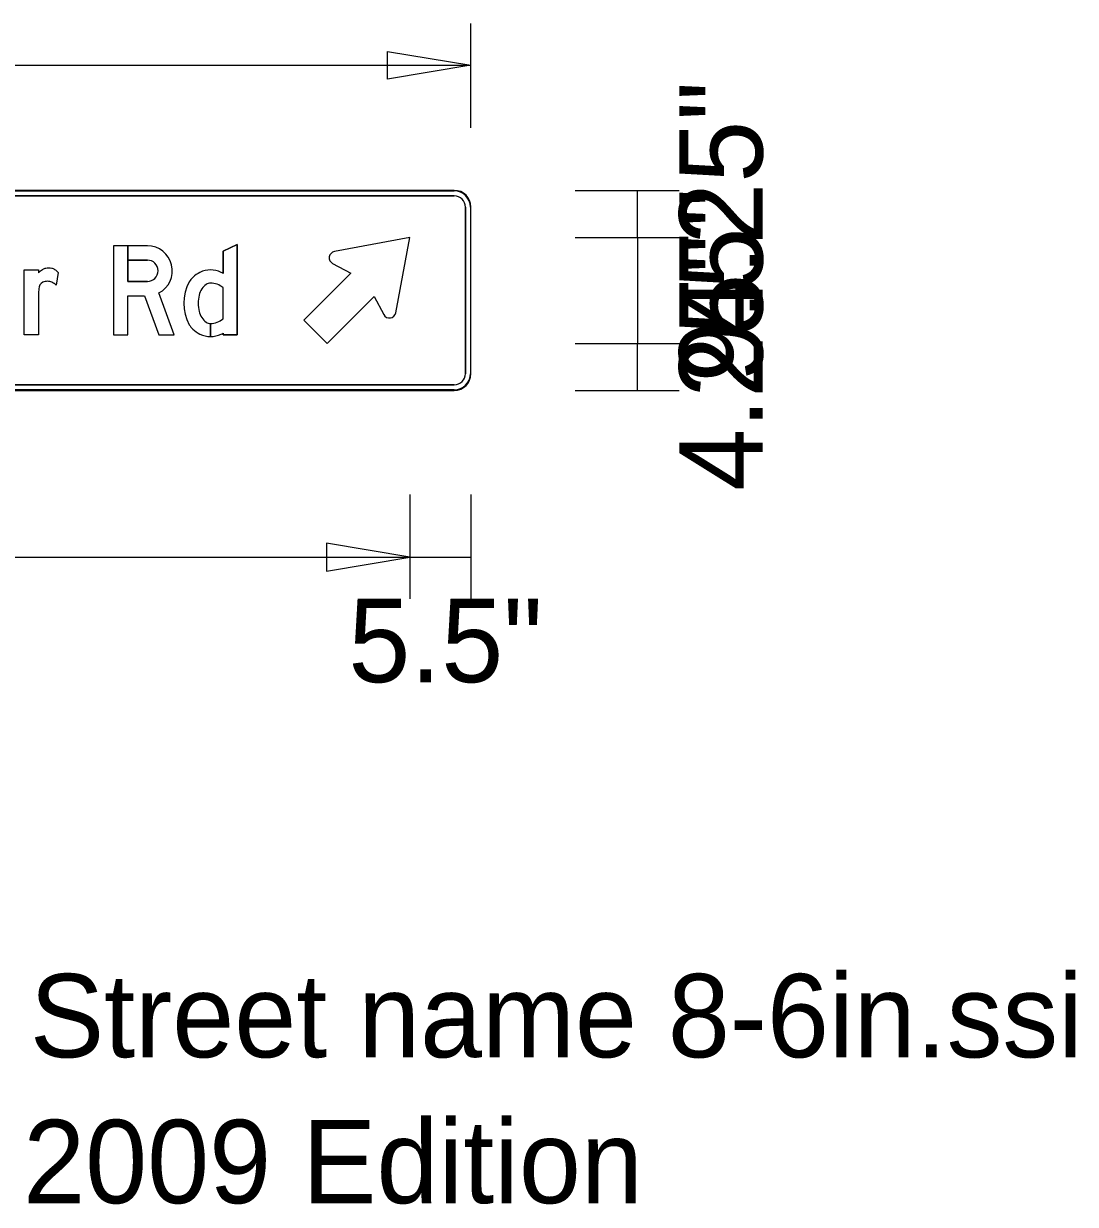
# Model space of a CAD drawing. Extents: x 914742 to 915492, y 328736 to 329423.
# Drawn here: x 915005.88 to 915013.77, y 328736.13 to 328744.99 of the extents above; entities that cross this region are included whole.
import ezdxf

# ---------------------------------------------------------------- set-up
doc = ezdxf.new("R2010")
doc.units = 0
for name, color, linetype in [('GSBWFILL', 7, 'Continuous'), ('GSCOLORFILL', 7, 'Continuous'), ('GSDIMS', 7, 'Continuous'), ('GSOUTLINE', 7, 'Continuous')]:
    doc.layers.add(name, color=color, linetype=linetype)

msp = doc.modelspace()

# ---------------------------------------------------------------- linework, layer by layer
at = {"layer": 'GSBWFILL'}
for p, q in [((915009.1129, 328743.7353), (915001.3629, 328743.7353)), ((915001.3629, 328743.6937), (915009.1129, 328743.6937)), ((915009.1962, 328743.6103), (915009.1962, 328742.3603)), ((915009.2379, 328742.3603), (915009.2379, 328743.6103)), ((915006.1423, 328743.1191), (915006.1281, 328743.0252)), ((915006.1423, 328743.1191), (915006.1423, 328743.1191)), ((915009.1129, 328742.277), (915001.3633, 328742.277)), ((915001.3633, 328742.2353), (915009.1129, 328742.2353))]:
    msp.add_line(p, q, dxfattribs=at)
for points in [[(915006.8121, 328743.052), (915006.6656, 328743.052), (915006.6656, 328743.3187), (915006.5589, 328743.3187), (915006.5589, 328742.652), (915006.6656, 328742.652), (915006.6656, 328742.9453), (915006.7908, 328742.9453), (915006.8986, 328742.652), (915007.0123, 328742.652), (915006.897, 328742.9657)], [(915006.6656, 328743.3187), (915006.6656, 328743.212), (915006.8121, 328743.212)], [(915006.8121, 328743.3187), (915006.6656, 328743.3187)], [(915007.3789, 328743.1129), (915007.3789, 328743.2787), (915007.4856, 328743.3303), (915007.4856, 328742.652), (915007.3789, 328742.652), (915007.3789, 328742.6644)], [(915008.6744, 328742.8173), (915008.7802, 328743.3826), (915008.2149, 328743.2768)], [(915005.9956, 328742.9572), (915005.9956, 328742.652), (915005.8889, 328742.652), (915005.8889, 328743.1387), (915005.9956, 328743.1387), (915005.9956, 328743.1168)], [(915008.2012, 328743.187), (915008.3374, 328743.1148), (915007.9856, 328742.763)], [(915007.3789, 328742.772), (915007.3789, 328743.0053)], [(915007.9856, 328742.763), (915008.1606, 328742.588), (915008.5124, 328742.9398), (915008.5846, 328742.8036)], [(915007.2856, 328742.737), (915007.2856, 328742.6387)], [(915007.2856, 328742.6387), (915007.2856, 328742.737)]]:
    msp.add_lwpolyline(points, dxfattribs=at)
for centre, radius, start, end in [((915009.1129, 328743.6103), 0.125, 0, 90), ((915009.1129, 328743.6103), 0.0833, 0, 90), ((915008.2237, 328743.2295), 0.0481, 100.60026, 242.05729), ((915008.6271, 328742.8262), 0.0481, 207.94271, 349.39974), ((915009.1129, 328742.3603), 0.125, 270, 0), ((915009.1129, 328742.3603), 0.0833, 270, 0)]:
    msp.add_arc(centre, radius, start, end, dxfattribs=at)
for centre, major_axis, ratio, start_param, end_param in [((915006.8121, 328743.132), (0, 0.1867), 0.999999, 3.613317, 6.283185), ((915006.8121, 328743.132), (0, 0.08), 0.999999, 3.141593, 6.283185), ((915006.1238, 328742.9889), (0, 0.181), 0.999992, 0.581368, 0.786698), ((915006.061, 328743.0845), (0, 0.0667), 0.999992, 0.152837, 0.581368), ((915006.0713, 328743.0175), (0, 0.1345), 0.999992, 0, 0.152837), ((915006.0713, 328743.0272), (0, 0.1248), 0.999992, 6.089185, 6.283185), ((915006.0825, 328743.0842), (0, 0.0667), 0.999992, 5.719052, 6.089185), ((915006.0648, 328743.0563), (0, 0.0997), 0.999992, 5.39423, 5.719052), ((915007.3019, 328742.9243), (0, 0.2181), 0.999993, 0.454071, 0.759609), ((915007.2856, 328742.9577), (0, 0.181), 0.999993, 6.283185, 6.737256), ((915007.2856, 328742.9577), (0, 0.181), 0.999993, 5.829115, 6.283185), ((915007.2693, 328742.9243), (0, 0.2181), 0.999993, 5.756638, 5.829115), ((915006.0535, 328742.9975), (0, 0.0558), 0.999992, 0.483758, 1.563151), ((915006.0642, 328742.9461), (0, 0.1073), 0.999992, 0, 0.348596), ((915006.0642, 328742.9752), (0, 0.0783), 0.999992, 5.88958, 6.283185), ((915006.0091, 328742.8806), (0, 0.1873), 0.999992, 5.594805, 5.811282), ((915007.4232, 328742.8887), (0, 0.3376), 0.999993, 1.075368, 2.066224), ((915007.2435, 328742.9858), (0, 0.1333), 0.999993, 0.759609, 1.075368), ((915007.3154, 328742.937), (0, 0.1124), 0.999993, 0.592441, 1.019141), ((915007.2856, 328742.9812), (0, 0.0591), 0.999993, 6.283185, 6.875627), ((915007.2856, 328742.8984), (0, 0.1419), 0.999993, 5.565644, 6.283185), ((915006.3983, 328742.9572), (0, 0.4026), 0.999992, 1.469323, 1.570796), ((915007.4379, 328742.8887), (0, 0.2456), 0.999993, 1.321211, 1.570796), ((915007.3628, 328742.9078), (0, 0.1681), 0.999993, 1.019141, 1.321211), ((915007.4379, 328742.8887), (0, 0.2456), 0.999993, 1.570796, 1.820382), ((915007.3628, 328742.8695), (0, 0.1681), 0.999993, 1.820382, 2.122451), ((915007.3154, 328742.8403), (0, 0.1124), 0.999993, 2.122451, 2.549151), ((915007.2856, 328742.8789), (0, 0.1419), 0.999993, 3.14171, 3.859134), ((915007.2435, 328742.7915), (0, 0.1333), 0.999993, 2.066224, 2.381983), ((915007.3019, 328742.853), (0, 0.2181), 0.999993, 2.381983, 2.687522), ((915007.2856, 328742.7961), (0, 0.0591), 0.999993, 2.549151, 3.141593), ((915007.2856, 328742.8197), (0, 0.181), 0.999993, 2.687522, 3.141593), ((915007.2856, 328742.8197), (0, 0.181), 0.999993, 3.141685, 3.595663), ((915007.2693, 328742.853), (0, 0.2181), 0.999993, 3.595663, 3.66814)]:
    msp.add_ellipse(centre, major_axis=major_axis, ratio=ratio, start_param=start_param, end_param=end_param, dxfattribs=at)
at = {"layer": 'GSCOLORFILL'}
for p, q in [((915009.1129, 328743.7353), (915001.3629, 328743.7353)), ((915009.1129, 328743.7353), (915001.3629, 328743.7353)), ((915009.1129, 328743.7353), (915001.3629, 328743.7353)), ((915001.3629, 328743.7312), (915009.1129, 328743.7312)), ((915001.3629, 328743.6937), (915009.1129, 328743.6937)), ((915009.1962, 328743.6103), (915009.1962, 328742.3603)), ((915009.2337, 328743.6103), (915009.2337, 328742.3603)), ((915009.2379, 328742.3603), (915009.2379, 328743.6103)), ((915009.2379, 328742.3603), (915009.2379, 328743.6103)), ((915009.2379, 328742.3603), (915009.2379, 328743.6103)), ((915006.1423, 328743.1191), (915006.1281, 328743.0252)), ((915006.1423, 328743.1191), (915006.1423, 328743.1191)), ((915009.1129, 328742.2395), (915001.3629, 328742.2395)), ((915001.3629, 328742.2353), (915009.1129, 328742.2353)), ((915001.3629, 328742.2353), (915009.1129, 328742.2353)), ((915009.1129, 328742.277), (915001.3633, 328742.277)), ((915001.3633, 328742.2353), (915009.1129, 328742.2353))]:
    msp.add_line(p, q, dxfattribs=at)
for points in [[(915006.8121, 328743.052), (915006.6656, 328743.052), (915006.6656, 328743.3187), (915006.5589, 328743.3187), (915006.5589, 328742.652), (915006.6656, 328742.652), (915006.6656, 328742.9453), (915006.7908, 328742.9453), (915006.8986, 328742.652), (915007.0123, 328742.652), (915006.897, 328742.9657)], [(915006.6656, 328743.3187), (915006.6656, 328743.212), (915006.8121, 328743.212)], [(915006.8121, 328743.3187), (915006.6656, 328743.3187)], [(915007.3789, 328743.1129), (915007.3789, 328743.2787), (915007.4856, 328743.3303), (915007.4856, 328742.652), (915007.3789, 328742.652), (915007.3789, 328742.6644)], [(915008.6744, 328742.8173), (915008.7802, 328743.3826), (915008.2149, 328743.2768)], [(915005.9956, 328742.9572), (915005.9956, 328742.652), (915005.8889, 328742.652), (915005.8889, 328743.1387), (915005.9956, 328743.1387), (915005.9956, 328743.1168)], [(915008.2012, 328743.187), (915008.3374, 328743.1148), (915007.9856, 328742.763)], [(915007.3789, 328742.772), (915007.3789, 328743.0053)], [(915007.9856, 328742.763), (915008.1606, 328742.588), (915008.5124, 328742.9398), (915008.5846, 328742.8036)], [(915007.2856, 328742.737), (915007.2856, 328742.6387)], [(915007.2856, 328742.6387), (915007.2856, 328742.737)]]:
    msp.add_lwpolyline(points, dxfattribs=at)
for centre, radius, start, end in [((915009.1129, 328743.6103), 0.125, 0, 90), ((915009.1129, 328743.6103), 0.125, 0, 90), ((915009.1129, 328743.6103), 0.125, 0, 90), ((915009.1129, 328743.6103), 0.1208, 0, 90), ((915009.1129, 328743.6103), 0.0833, 0, 90), ((915008.2237, 328743.2295), 0.0481, 100.60026, 242.05729), ((915008.6271, 328742.8262), 0.0481, 207.94271, 349.39974), ((915009.1129, 328742.3603), 0.125, 270, 0), ((915009.1129, 328742.3603), 0.125, 270, 0), ((915009.1129, 328742.3603), 0.0833, 270, 0), ((915009.1129, 328742.3603), 0.125, 270, 0), ((915009.1129, 328742.3603), 0.1208, 270, 0)]:
    msp.add_arc(centre, radius, start, end, dxfattribs=at)
for centre, major_axis, ratio, start_param, end_param in [((915006.8121, 328743.132), (0, 0.1867), 0.999999, 3.613317, 6.283185), ((915006.8121, 328743.132), (0, 0.08), 0.999999, 3.141593, 6.283185), ((915006.1238, 328742.9889), (0, 0.181), 0.999992, 0.581368, 0.786698), ((915006.061, 328743.0845), (0, 0.0667), 0.999992, 0.152837, 0.581368), ((915006.0713, 328743.0175), (0, 0.1345), 0.999992, 0, 0.152837), ((915006.0713, 328743.0272), (0, 0.1248), 0.999992, 6.089185, 6.283185), ((915006.0825, 328743.0842), (0, 0.0667), 0.999992, 5.719052, 6.089185), ((915006.0648, 328743.0563), (0, 0.0997), 0.999992, 5.39423, 5.719052), ((915007.3019, 328742.9243), (0, 0.2181), 0.999993, 0.454071, 0.759609), ((915007.2856, 328742.9577), (0, 0.181), 0.999993, 6.283185, 6.737256), ((915007.2856, 328742.9577), (0, 0.181), 0.999993, 5.829115, 6.283185), ((915007.2693, 328742.9243), (0, 0.2181), 0.999993, 5.756638, 5.829115), ((915006.0535, 328742.9975), (0, 0.0558), 0.999992, 0.483758, 1.563151), ((915006.0642, 328742.9461), (0, 0.1073), 0.999992, 0, 0.348596), ((915006.0642, 328742.9752), (0, 0.0783), 0.999992, 5.88958, 6.283185), ((915006.0091, 328742.8806), (0, 0.1873), 0.999992, 5.594805, 5.811282), ((915007.4232, 328742.8887), (0, 0.3376), 0.999993, 1.075368, 2.066224), ((915007.2435, 328742.9858), (0, 0.1333), 0.999993, 0.759609, 1.075368), ((915007.3154, 328742.937), (0, 0.1124), 0.999993, 0.592441, 1.019141), ((915007.2856, 328742.9812), (0, 0.0591), 0.999993, 6.283185, 6.875627), ((915007.2856, 328742.8984), (0, 0.1419), 0.999993, 5.565644, 6.283185), ((915006.3983, 328742.9572), (0, 0.4026), 0.999992, 1.469323, 1.570796), ((915007.4379, 328742.8887), (0, 0.2456), 0.999993, 1.321211, 1.570796), ((915007.3628, 328742.9078), (0, 0.1681), 0.999993, 1.019141, 1.321211), ((915007.4379, 328742.8887), (0, 0.2456), 0.999993, 1.570796, 1.820382), ((915007.3628, 328742.8695), (0, 0.1681), 0.999993, 1.820382, 2.122451), ((915007.3154, 328742.8403), (0, 0.1124), 0.999993, 2.122451, 2.549151), ((915007.2856, 328742.8789), (0, 0.1419), 0.999993, 3.14171, 3.859134), ((915007.2435, 328742.7915), (0, 0.1333), 0.999993, 2.066224, 2.381983), ((915007.3019, 328742.853), (0, 0.2181), 0.999993, 2.381983, 2.687522), ((915007.2856, 328742.7961), (0, 0.0591), 0.999993, 2.549151, 3.141593), ((915007.2856, 328742.8197), (0, 0.181), 0.999993, 2.687522, 3.141593), ((915007.2856, 328742.8197), (0, 0.181), 0.999993, 3.141685, 3.595663), ((915007.2693, 328742.853), (0, 0.2181), 0.999993, 3.595663, 3.66814)]:
    msp.add_ellipse(centre, major_axis=major_axis, ratio=ratio, start_param=start_param, end_param=end_param, dxfattribs=at)
at = {"layer": 'GSDIMS'}
for p, q in [((915009.2379, 328744.2041), (915009.2379, 328744.9853)), ((915001.2379, 328744.6728), (915009.2379, 328744.6728)), ((915009.2379, 328744.2041), (915009.2379, 328744.2041)), ((915010.0191, 328743.7353), (915010.8004, 328743.7353)), ((915010.0191, 328743.7353), (915010.0191, 328743.7353)), ((915010.4879, 328743.3826), (915010.4879, 328743.7353)), ((915010.0191, 328743.3826), (915010.8004, 328743.3826)), ((915010.0191, 328743.3826), (915010.8004, 328743.3826)), ((915010.4879, 328743.3826), (915010.4879, 328742.588)), ((915010.0191, 328742.588), (915010.8004, 328742.588)), ((915010.0191, 328742.588), (915010.8004, 328742.588)), ((915010.4879, 328742.2353), (915010.4879, 328742.588)), ((915010.0191, 328742.2353), (915010.8004, 328742.2353)), ((915010.0191, 328742.2353), (915010.0191, 328742.2353)), ((915008.7802, 328741.4541), (915008.7802, 328740.6728)), ((915008.7802, 328741.4541), (915008.7802, 328740.6728)), ((915009.2379, 328741.4541), (915009.2379, 328740.6728)), ((915009.2379, 328741.4541), (915009.2379, 328740.6728)), ((915001.6956, 328740.9853), (915008.7802, 328740.9853)), ((915008.7802, 328740.9853), (915009.2379, 328740.9853))]:
    msp.add_line(p, q, dxfattribs=at)
for points in [[(915009.2379, 328744.6728), (915008.6129, 328744.5687), (915008.6129, 328744.777)], [(915008.7802, 328740.9853), (915008.1552, 328741.0895), (915008.1552, 328740.8812)]]:
    msp.add_lwpolyline(points, close=True, dxfattribs=at)
at = {"layer": 'GSOUTLINE'}
for p, q in [((915009.1129, 328743.7353), (915001.3629, 328743.7353)), ((915009.1129, 328743.6937), (915001.3629, 328743.6937)), ((915009.1962, 328742.3603), (915009.1962, 328743.6103)), ((915009.2379, 328742.3603), (915009.2379, 328743.6103)), ((915006.1423, 328743.1191), (915006.1281, 328743.0252)), ((915006.1423, 328743.1191), (915006.1423, 328743.1191)), ((915001.3629, 328742.277), (915009.1129, 328742.277)), ((915001.3629, 328742.2353), (915009.1129, 328742.2353))]:
    msp.add_line(p, q, dxfattribs=at)
for points in [[(915006.8121, 328743.3187), (915006.5589, 328743.3187), (915006.5589, 328742.652), (915006.6656, 328742.652), (915006.6656, 328742.9453), (915006.7908, 328742.9453), (915006.8986, 328742.652), (915007.0123, 328742.652), (915006.897, 328742.9657)], [(915007.3789, 328742.6644), (915007.3789, 328742.652), (915007.4856, 328742.652), (915007.4856, 328743.3303), (915007.3789, 328743.2787), (915007.3789, 328743.1129)], [(915008.6744, 328742.8173), (915008.7802, 328743.3826), (915008.2149, 328743.2768)], [(915006.8121, 328743.212), (915006.6656, 328743.212), (915006.6656, 328743.052), (915006.8121, 328743.052)], [(915005.9956, 328742.9572), (915005.9956, 328742.652), (915005.8889, 328742.652), (915005.8889, 328743.1387), (915005.9956, 328743.1387), (915005.9956, 328743.1168)], [(915008.2012, 328743.187), (915008.3374, 328743.1148), (915007.9856, 328742.763)], [(915007.3789, 328742.772), (915007.3789, 328743.0053)], [(915007.9856, 328742.763), (915008.1606, 328742.588), (915008.5124, 328742.9398), (915008.5846, 328742.8036)]]:
    msp.add_lwpolyline(points, dxfattribs=at)
for centre, radius, start, end in [((915009.1129, 328743.6103), 0.125, 0, 90), ((915009.1129, 328743.6103), 0.0833, 0, 90), ((915008.2237, 328743.2295), 0.0481, 100.60026, 242.05729), ((915008.6271, 328742.8262), 0.0481, 207.94271, 349.39974), ((915009.1129, 328742.3603), 0.125, 270, 0), ((915009.1129, 328742.3603), 0.0833, 270, 0)]:
    msp.add_arc(centre, radius, start, end, dxfattribs=at)
for centre, major_axis, ratio, start_param, end_param in [((915006.8121, 328743.132), (0, 0.1867), 0.999999, 3.613317, 6.283185), ((915006.8121, 328743.132), (0, 0.08), 0.999999, 3.141593, 6.283185), ((915006.1238, 328742.9889), (0, 0.181), 0.999992, 0.581368, 0.786698), ((915006.061, 328743.0845), (0, 0.0667), 0.999992, 0.152837, 0.581368), ((915006.0713, 328743.0175), (0, 0.1345), 0.999992, 0, 0.152837), ((915006.0713, 328743.0272), (0, 0.1248), 0.999992, 6.089185, 6.283185), ((915006.0825, 328743.0842), (0, 0.0667), 0.999992, 5.719052, 6.089185), ((915006.0648, 328743.0563), (0, 0.0997), 0.999992, 5.39423, 5.719052), ((915007.3019, 328742.9243), (0, 0.2181), 0.999993, 0.454071, 0.759609), ((915007.2856, 328742.9577), (0, 0.181), 0.999993, 6.283185, 6.737256), ((915007.2856, 328742.9577), (0, 0.181), 0.999993, 5.829115, 6.283185), ((915007.2693, 328742.9243), (0, 0.2181), 0.999993, 5.756638, 5.829115), ((915006.0535, 328742.9975), (0, 0.0558), 0.999992, 0.483758, 1.563151), ((915006.0642, 328742.9461), (0, 0.1073), 0.999992, 0, 0.348596), ((915006.0642, 328742.9752), (0, 0.0783), 0.999992, 5.88958, 6.283185), ((915006.0091, 328742.8806), (0, 0.1873), 0.999992, 5.594805, 5.811282), ((915007.4232, 328742.8887), (0, 0.3376), 0.999993, 1.075368, 2.066224), ((915007.2435, 328742.9858), (0, 0.1333), 0.999993, 0.759609, 1.075368), ((915007.3154, 328742.937), (0, 0.1124), 0.999993, 0.592441, 1.019141), ((915007.2856, 328742.9812), (0, 0.0591), 0.999993, 6.283185, 6.875627), ((915007.2856, 328742.8984), (0, 0.1419), 0.999993, 5.565644, 6.283185), ((915006.3983, 328742.9572), (0, 0.4026), 0.999992, 1.469323, 1.570796), ((915007.4379, 328742.8887), (0, 0.2456), 0.999993, 1.321211, 1.570796), ((915007.3628, 328742.9078), (0, 0.1681), 0.999993, 1.019141, 1.321211), ((915007.4379, 328742.8887), (0, 0.2456), 0.999993, 1.570796, 1.820382), ((915007.3628, 328742.8695), (0, 0.1681), 0.999993, 1.820382, 2.122451), ((915007.3154, 328742.8403), (0, 0.1124), 0.999993, 2.122451, 2.549151), ((915007.2856, 328742.8789), (0, 0.1419), 0.999993, 3.141593, 3.859134), ((915007.2435, 328742.7915), (0, 0.1333), 0.999993, 2.066224, 2.381983), ((915007.3019, 328742.853), (0, 0.2181), 0.999993, 2.381983, 2.687522), ((915007.2856, 328742.7961), (0, 0.0591), 0.999993, 2.549151, 3.141593), ((915007.2856, 328742.8197), (0, 0.181), 0.999993, 2.687522, 3.141593), ((915007.2856, 328742.8197), (0, 0.181), 0.999993, 3.141685, 3.595663), ((915007.2856, 328742.8197), (0, 0.181), 0.999993, 3.141593, 3.141685), ((915007.2693, 328742.853), (0, 0.2181), 0.999993, 3.595663, 3.66814)]:
    msp.add_ellipse(centre, major_axis=major_axis, ratio=ratio, start_param=start_param, end_param=end_param, dxfattribs=at)

# ---------------------------------------------------------------- texts
at = {"layer": 'GSDIMS'}
for s, p in [('4.25"', (915011.4254, 328742.6304)), ('9.5"', (915011.4254, 328742.2949)), ('4.25"', (915011.4254, 328741.4831))]:
    msp.add_text(s, height=0.625, rotation=90, dxfattribs=at).set_placement(p)
for s, p in [('5.5"', (915008.3186, 328740.0478)), ('Panel Style: Street name 8-6in.ssi', (915001.2379, 328737.2353)), ('M.U.T.C.D.: 2009 Edition', (915001.2379, 328736.1416))]:
    msp.add_text(s, height=0.625, dxfattribs=at).set_placement(p)

doc.saveas('drawing.dxf')
